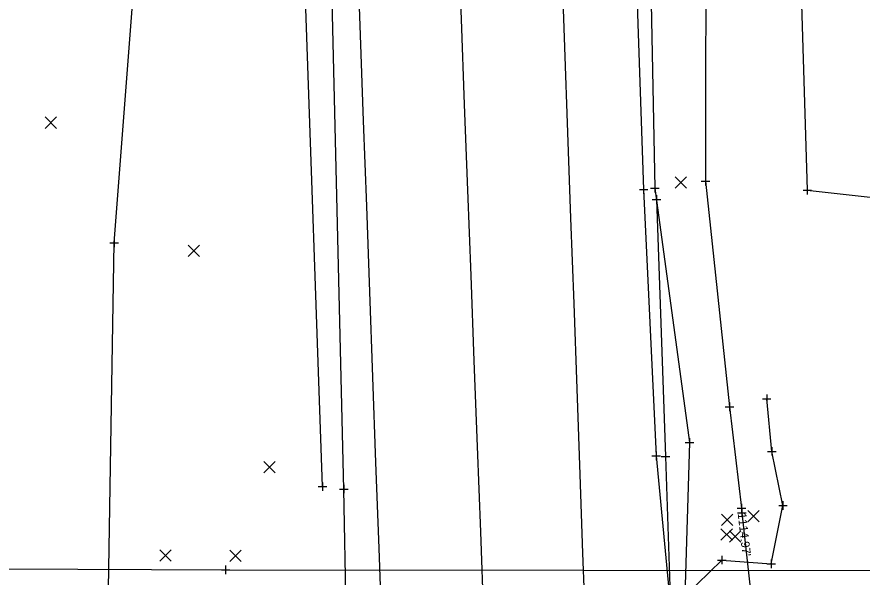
# Model space of a CAD drawing. Extents: x 146022 to 147632, y 437624 to 440659.
# Drawn here: x 146968.6 to 147067.5, y 438664.4 to 438729.9 of the extents above; entities that cross this region are included whole.
import ezdxf

# ---------------------------------------------------------------- set-up
doc = ezdxf.new("R2010")
doc.units = 0
for name, color, linetype in [('_CIVIL_CONSTRUCTION', 7, 'Continuous'), ('DR_Channel', 7, 'Continuous'), ('DR_P_Paved_Gutter', 7, 'Continuous'), ('DR_X_Storm_Sewer', 7, 'Continuous'), ('GE_P_Alignment_100_Distances', 7, 'Continuous'), ('PF_X_Ground_Line', 7, 'Continuous'), ('PV_P_Curb', 7, 'Continuous'), ('PV_P_Saw_Cut_Line', 7, 'Continuous'), ('RD_P_Anchor_Assembly', 7, 'Continuous'), ('RD_P_Fence', 7, 'Continuous'), ('RD_P_GR_Lt_Replaced', 7, 'Continuous'), ('SC_Scratch1', 7, 'Continuous'), ('SC_Scratch3', 7, 'Continuous'), ('UT_X_Overhead_Electric', 7, 'Continuous')]:
    doc.layers.add(name, color=color, linetype=linetype)

msp = doc.modelspace()

# ---------------------------------------------------------------- linework, layer by layer
at = {"layer": '_CIVIL_CONSTRUCTION'}
for p, q in [((146971.855, 438716.894), (146973.188, 438718.229)), ((146971.855, 438718.229), (146973.188, 438716.894)), ((147045.602, 438709.899), (147046.935, 438711.234)), ((147045.602, 438711.234), (147046.935, 438709.899)), ((146988.585, 438701.916), (146989.918, 438703.251)), ((146988.585, 438703.251), (146989.918, 438701.916)), ((146997.455, 438676.624), (146998.788, 438677.959)), ((146997.455, 438677.959), (146998.788, 438676.624)), ((147054.115, 438670.883), (147055.448, 438672.218)), ((147054.115, 438672.218), (147055.448, 438670.883)), ((147051.027, 438670.444), (147052.36, 438671.779)), ((147051.027, 438671.779), (147052.36, 438670.444)), ((147050.957, 438668.747), (147052.29, 438670.082)), ((147050.957, 438670.082), (147052.29, 438668.747)), ((147051.951, 438668.493), (147053.284, 438669.828)), ((147051.951, 438669.828), (147053.284, 438668.493)), ((146985.286, 438666.294), (146986.62, 438667.629)), ((146985.286, 438667.629), (146986.62, 438666.294)), ((146993.476, 438666.251), (146994.809, 438667.586)), ((146993.476, 438667.586), (146994.809, 438666.251))]:
    msp.add_line(p, q, dxfattribs=at)
at = {"layer": 'DR_Channel'}
msp.add_lwpolyline([(147043.412, 438708.595), (147044.478, 438678.513), (147045.162, 438657.493)], dxfattribs=at)
at = {"layer": 'DR_P_Paved_Gutter'}
msp.add_lwpolyline([(146978.603, 438595.669), (146978.94, 438641.642), (146979.937, 438703.502), (146984.388, 438761.316), (146986.686, 438784.307)], dxfattribs=at)
at = {"layer": 'DR_X_Storm_Sewer'}
msp.add_line((147053.412, 438671.931), (147066.551, 438554.767), dxfattribs=at)
at = {"layer": 'GE_P_Alignment_100_Distances'}
msp.add_lwpolyline([(146750.217, 438665.831), (146889.211, 438665.725), (146992.985, 438665.287), (147118.645, 438665.141)], dxfattribs=at)
at = {"layer": 'PF_X_Ground_Line'}
for points in [[(147031.265, 439100.493), (147033.124, 439049.689), (147035.536, 438989.571), (147036.948, 438926.083), (147039.28, 438864.722), (147041.137, 438801.73), (147042.54, 438743.359), (147043.212, 438709.888), (147047.269, 438680.177), (147046.71, 438662.178), (147051.053, 438666.422), (147056.824, 438665.984), (147058.213, 438672.792), (147056.903, 438679.132), (147056.31, 438685.267)], [(147004.321, 438675.007), (147002.253, 438734.292), (147000.945, 438785.222)]]:
    msp.add_lwpolyline(points, dxfattribs=at)
at = {"layer": 'PV_P_Curb'}
msp.add_lwpolyline([(147023.6, 438649.734), (147023.222, 438659.727), (147022.845, 438669.72), (147022.467, 438679.713), (147022.09, 438689.706), (147021.712, 438699.699), (147021.334, 438709.691), (147020.957, 438719.684), (147020.579, 438729.677), (147020.202, 438739.67), (147019.824, 438749.663), (147019.447, 438759.656), (147019.069, 438769.649), (147018.692, 438779.642), (147018.314, 438789.634), (147017.936, 438799.627), (147017.559, 438809.62), (147017.181, 438819.613), (147016.804, 438829.606), (147016.426, 438839.599), (147016.049, 438849.592), (147015.671, 438859.584)], dxfattribs=at)
at = {"layer": 'PV_P_Saw_Cut_Line'}
msp.add_lwpolyline([(147094.024, 438852.124), (147057.419, 438828.573), (147061.065, 438709.676), (147089.484, 438706.496), (147094.287, 438706.688)], dxfattribs=at)
at = {"layer": 'RD_P_Anchor_Assembly'}
for p, q in [((147048.65, 438710.721), (147049.65, 438710.721)), ((147049.15, 438711.221), (147049.15, 438710.221)), ((147049.15, 438710.721), (147049.15, 438710.721)), ((147041.41, 438709.752), (147042.41, 438709.752)), ((147041.91, 438710.252), (147041.91, 438709.252)), ((147041.91, 438709.752), (147041.91, 438709.752)), ((147042.712, 438709.888), (147043.712, 438709.888)), ((147043.212, 438710.388), (147043.212, 438709.388)), ((147043.212, 438709.888), (147043.212, 438709.888)), ((147061.065, 438710.176), (147061.065, 438709.176)), ((147043.412, 438709.095), (147043.412, 438708.095)), ((147060.565, 438709.676), (147061.565, 438709.676)), ((147061.065, 438709.676), (147061.065, 438709.676)), ((147042.912, 438708.595), (147043.912, 438708.595)), ((147043.412, 438708.595), (147043.412, 438708.595)), ((146979.937, 438704.002), (146979.937, 438703.002)), ((146979.437, 438703.502), (146980.437, 438703.502)), ((146979.937, 438703.502), (146979.937, 438703.502)), ((147055.81, 438685.267), (147056.81, 438685.267)), ((147056.31, 438685.767), (147056.31, 438684.767)), ((147056.31, 438685.267), (147056.31, 438685.267)), ((147051.458, 438684.331), (147052.458, 438684.331)), ((147051.958, 438684.831), (147051.958, 438683.831)), ((147051.958, 438684.331), (147051.958, 438684.331)), ((147046.769, 438680.177), (147047.769, 438680.177)), ((147047.269, 438680.677), (147047.269, 438679.677)), ((147047.269, 438680.177), (147047.269, 438680.177)), ((147043.365, 438679.113), (147043.365, 438678.113)), ((147056.403, 438679.132), (147057.403, 438679.132)), ((147056.903, 438679.632), (147056.903, 438678.632)), ((147056.903, 438679.132), (147056.903, 438679.132)), ((147042.865, 438678.613), (147043.865, 438678.613)), ((147043.365, 438678.613), (147043.365, 438678.613)), ((147043.978, 438678.513), (147044.978, 438678.513)), ((147044.478, 438679.013), (147044.478, 438678.013)), ((147044.478, 438678.513), (147044.478, 438678.513)), ((147004.321, 438675.507), (147004.321, 438674.507)), ((147006.832, 438675.225), (147006.832, 438674.225)), ((147003.821, 438675.007), (147004.821, 438675.007)), ((147004.321, 438675.007), (147004.321, 438675.007)), ((147006.332, 438674.725), (147007.332, 438674.725)), ((147006.832, 438674.725), (147006.832, 438674.725)), ((147058.213, 438673.292), (147058.213, 438672.292)), ((147052.85, 438672.493), (147053.85, 438672.493)), ((147053.35, 438672.993), (147053.35, 438671.993)), ((147053.35, 438672.493), (147053.35, 438672.493)), ((147057.713, 438672.792), (147058.713, 438672.792)), ((147058.213, 438672.792), (147058.213, 438672.792)), ((147050.553, 438666.422), (147051.553, 438666.422)), ((147051.053, 438666.922), (147051.053, 438665.922)), ((147051.053, 438666.422), (147051.053, 438666.422)), ((147056.824, 438666.484), (147056.824, 438665.484)), ((146992.485, 438665.287), (146993.485, 438665.287)), ((146992.985, 438665.787), (146992.985, 438664.787)), ((146992.985, 438665.287), (146992.985, 438665.287)), ((147056.324, 438665.984), (147057.324, 438665.984)), ((147056.824, 438665.984), (147056.824, 438665.984))]:
    msp.add_line(p, q, dxfattribs=at)
at = {"layer": 'RD_P_Fence'}
msp.add_lwpolyline([(147038.399, 439102.595), (147039.773, 439045.265), (147042.106, 438990.254), (147044.492, 438926.83), (147045.821, 438865.737), (147047.925, 438802.84), (147049.204, 438744.738), (147049.15, 438710.721), (147051.958, 438684.331), (147053.35, 438672.493)], dxfattribs=at)
at = {"layer": 'RD_P_GR_Lt_Replaced'}
for points in [[(147007.624, 438631.915), (147006.832, 438674.725), (147005.435, 438733.475), (147003.268, 438784.298), (147000.579, 438849.422), (146998.523, 438912.12), (146996.336, 438976.527), (146994.653, 439039.1), (146992.525, 439098.481), (146992.611, 439099.809)], [(147028.78, 439100.289), (147030.702, 439050.099), (147032.83, 438989.568), (147034.209, 438926.711), (147035.765, 438865.146), (147038.939, 438801.428), (147040.729, 438744.008), (147041.91, 438709.752), (147043.365, 438678.613), (147045.134, 438660.085), (147045.684, 438643.984), (147046.174, 438628.211), (147046.868, 438610.995), (147047.321, 438600.784)]]:
    msp.add_lwpolyline(points, dxfattribs=at)
at = {"layer": 'SC_Scratch3'}
for points in [[(147011.665, 438647.832), (147011.304, 438657.825), (147010.943, 438667.819), (147010.582, 438677.812), (147010.221, 438687.806), (147009.86, 438697.799), (147009.499, 438707.793), (147009.139, 438717.786), (147008.778, 438727.78), (147008.417, 438737.773), (147008.056, 438747.767), (147007.695, 438757.76), (147007.334, 438767.754), (147006.973, 438777.747), (147006.612, 438787.741), (147006.251, 438797.734), (147005.89, 438807.728), (147005.529, 438817.721), (147005.169, 438827.715), (147004.808, 438837.708), (147004.447, 438847.702), (147004.086, 438857.695), (147003.725, 438867.689)], [(147027.903, 438858.713), (147028.253, 438848.719), (147028.336, 438846.326), (147028.695, 438836.333), (147029.054, 438826.339), (147029.413, 438816.345), (147029.772, 438806.352), (147030.131, 438796.358), (147030.49, 438786.365), (147030.849, 438776.371), (147031.208, 438766.378), (147031.567, 438756.384), (147031.926, 438746.391), (147032.285, 438736.397), (147032.644, 438726.403), (147033.003, 438716.41), (147033.362, 438706.416), (147033.721, 438696.423), (147034.08, 438686.429), (147034.439, 438676.436), (147034.769, 438667.24), (147035.152, 438657.247), (147035.503, 438648.06)]]:
    msp.add_lwpolyline(points, dxfattribs=at)
at = {"layer": 'UT_X_Overhead_Electric'}
for p, q in [((147053.412, 438672.431), (147053.412, 438671.431)), ((147052.912, 438671.931), (147053.912, 438671.931)), ((147053.412, 438671.931), (147053.412, 438671.931))]:
    msp.add_line(p, q, dxfattribs=at)

# ---------------------------------------------------------------- texts
at = {"layer": 'SC_Scratch1'}
msp.add_text("1114.97'", height=1, rotation=276.39843, dxfattribs=at).set_placement((147052.915, 438671.875))

doc.saveas('drawing.dxf')
